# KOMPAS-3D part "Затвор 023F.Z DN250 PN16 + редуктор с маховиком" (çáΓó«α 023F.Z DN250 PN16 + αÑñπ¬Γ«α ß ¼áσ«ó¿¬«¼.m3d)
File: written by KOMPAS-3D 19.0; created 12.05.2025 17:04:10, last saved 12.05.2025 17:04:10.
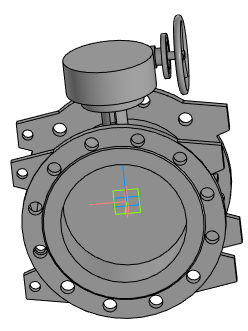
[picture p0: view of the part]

Document properties: Полное имя файла: Затвор 023F.Z DN250 PN16 + редуктор с маховиком.a3d

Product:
- Part/product: Затвор 023F.Z DN250 PN16 + редуктор с маховиком
    Масса: 77.4684

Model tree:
1. Операция без истории:1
